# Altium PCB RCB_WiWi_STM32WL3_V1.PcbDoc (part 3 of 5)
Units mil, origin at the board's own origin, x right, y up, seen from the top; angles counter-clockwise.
Board outline 1250.1 x 2647.64 mil, 10 copper layers (L01-TOP, L02-GND, L03-SIG, L04-GND, L05-PWR, L06-PWR, L07-GND, L08-SIG, L09-GND, L10-BOT), stack 62.1 mil thick; 342 components, 203 nets, 969 pads, 708 vias.
Unrouted connection lines stored in the file: 108.
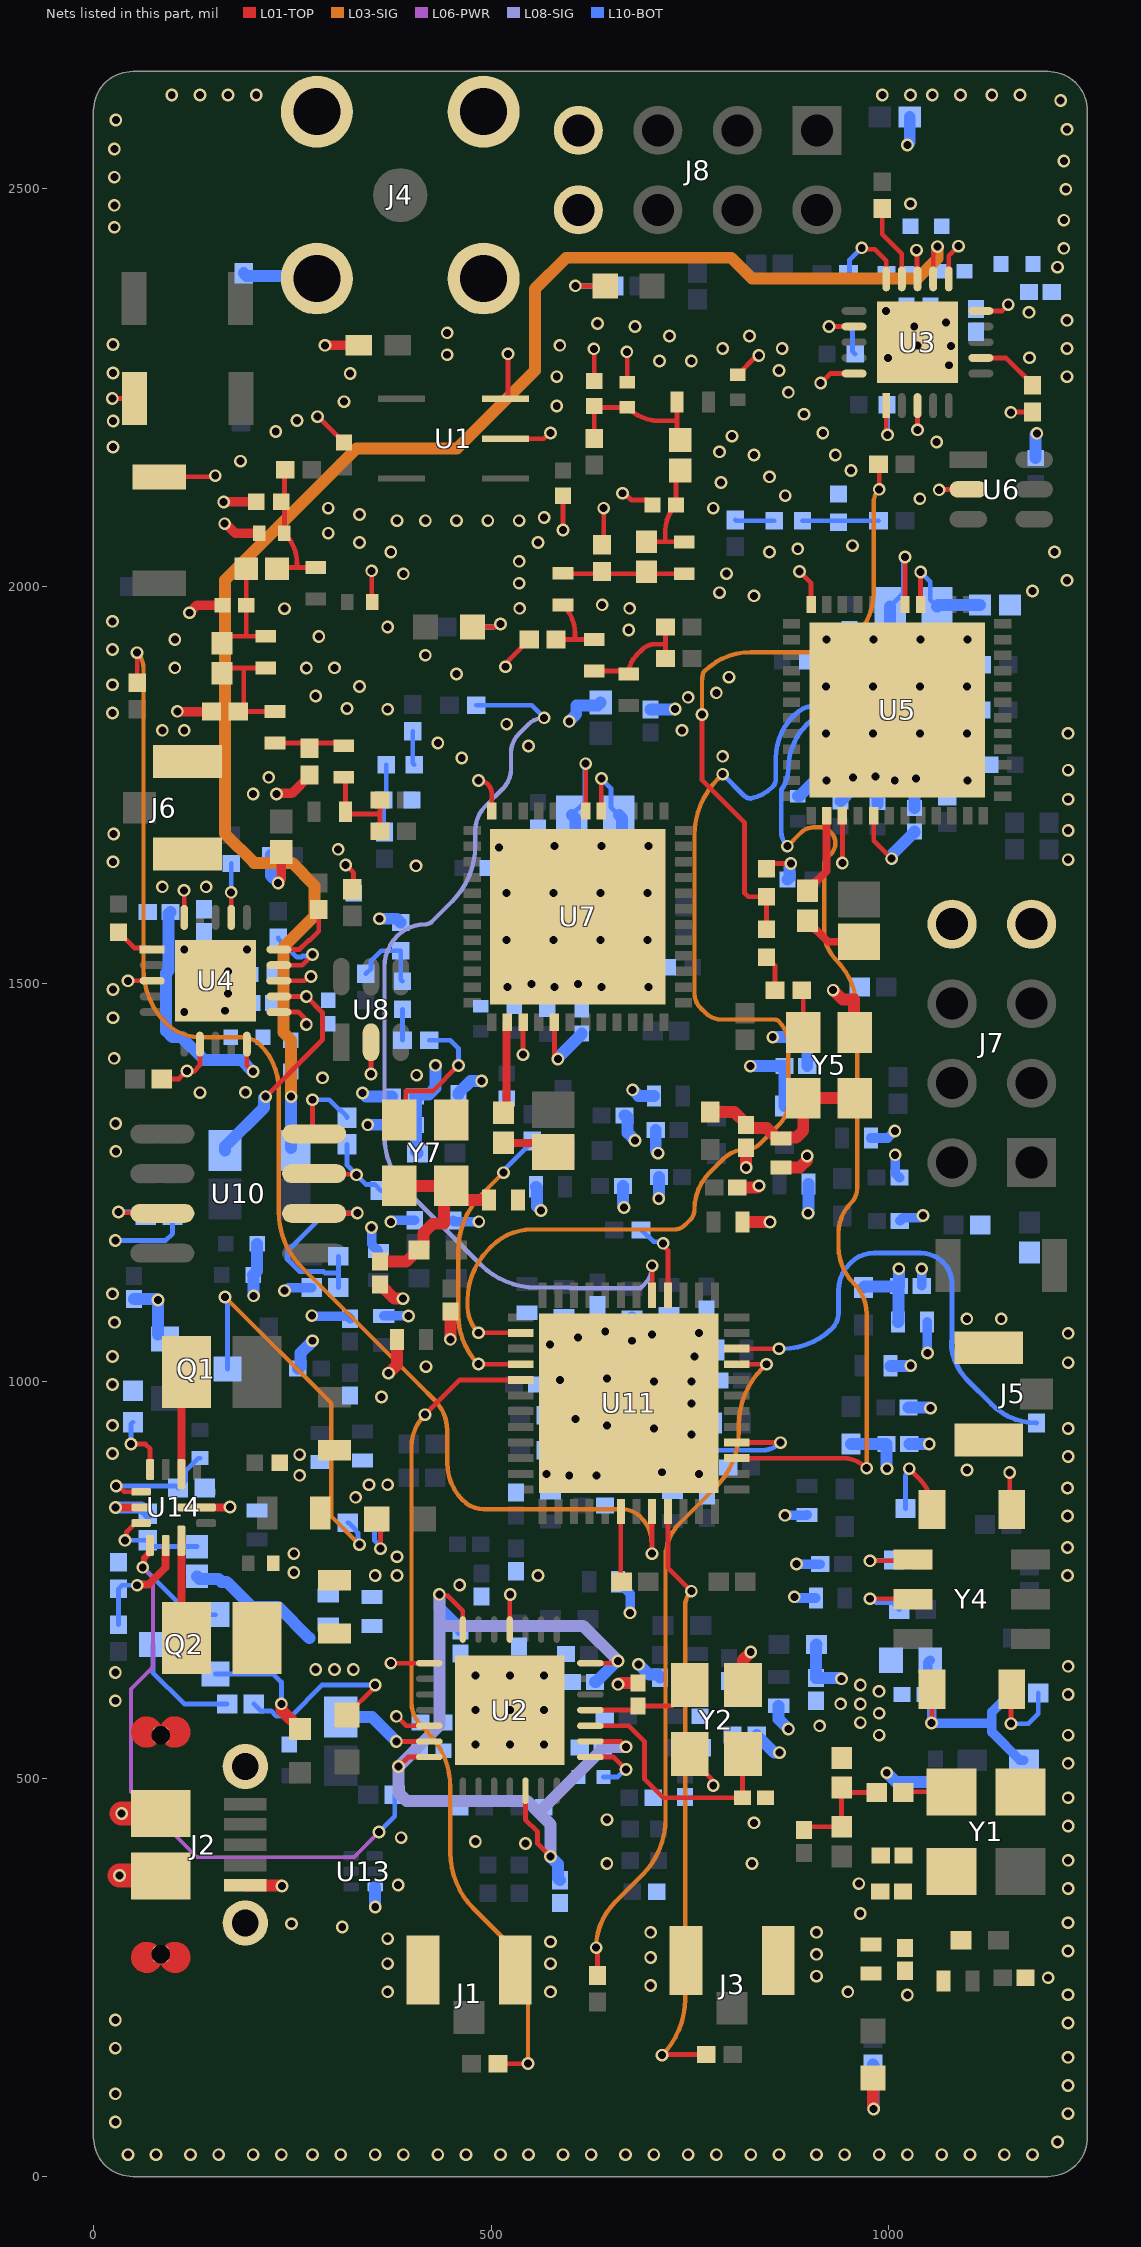
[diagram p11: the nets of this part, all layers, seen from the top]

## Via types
v1: diameter 16, hole 10, L01-TOP to L10-BOT, tented both sides, 699 vias
v2: diameter 16, hole 10, L01-TOP to L10-BOT, 9 vias

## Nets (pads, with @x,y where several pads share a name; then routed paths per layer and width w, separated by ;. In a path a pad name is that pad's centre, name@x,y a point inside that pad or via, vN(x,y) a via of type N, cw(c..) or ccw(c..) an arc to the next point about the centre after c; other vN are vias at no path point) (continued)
GND: C1.2 C2.2 C3.1 C5.2 C6.2 C7.2 C9.2 C10.2 C11.2 C12.2 C13.2 C14.1 C16.2 C17.2 C18.2 C20.2 C22.2 C23.2 C24.2 C25.2 C26.2 C27.2 C28.2 C29.2 C30.2 C31.2 C32.2 C33.2 C34.2 C35.2 C36.2 C37.2 C38.1 C39.2 C40.2 C41.2 C42.2 C43.2 C44.2 C45.1 C46.2 C47.2 C48.1 C49.2 C50.2 C51.2 C52.2 C53.1 C54.1 C55.2 C56.2 C57.1 C58.2 C59.2 C60.2 C61.1 C62.2 C63.2 C64.2 C65.2 C66.2 C67.2 C68.2 C69.2 C70.2 C71.2 C72.2 C73.2 C74.2 C75.2 C76.2 C77.2 C78.2 C79.2 C80.2 C81.2 C82.2 C83.2 C84.2 C85.2 C86.2 C87.2 C88.2 C89.2 C90.2 C91.2 C92.2 C93.2 C94.2 C95.2 C96.2 C97.2 C98.2 C99.2 C100.2 C101.2 C102.2 C103.2 C104.2 C105.2 C106.2 C107.2 C108.2 C109.2 C110.2 C111.2 C112.2 C113.2 C114.2 C115.2 C116.1 C117.2 C118.2 C119.2 C120.2 C121.2 C122.2 C123.1 C124.1 C125.2 C126.2 C127.2 C128.2 C129.2 C130.2 C131.2 C132.2 C133.2 C134.2 C135.2 C136.2 C137.2 C138.2 C139.2 C140.2 C141.1 C142.2 C143.2 C144.2 C145.2 C146.2 C147.2 C148.2 C149.2 C150.2 C151.2 C152.2 C153.2 C154.2 C155.2 C156.2 C157.1 C158.2 C159.2 D5.1 J1.2 J1.3 J2.5 J2.6 J2.7 J2.8 J2.9 J2.10 J2.11 J3.2 J3.3 J4.2 J4.3 J4.4 J4.5 J5.2 J5.3 J6.2 J6.3 J7.7 J7.8 J8.7 J8.8 Q1.2 Q2.2 R8.1 R10.1 R24.1 R25.1 R30.2 R45.2 R46.2 R56.1 R60.1 R61.1 R70.1 R73.2 R75.2 R77.1 R84.1 R88.1 R92.2 R97.1 R98.1 R100.2 R105.1 R109.1 R113.2 SW2.2 SW4.2 U1.1 U1.2 U2.18 U2.22 U2.26 U2.29 U3.3 U3.13 U3.21 U4.3 U4.13 U4.21 U5.24 U5.39 U5.49 U6.2 U7.24 U7.39 U7.49 U8.2 U10.4 U11.49 U13.3 U14.2 U14.9 Y1.2 Y2.2 Y2.4 Y4.5 Y5.2 Y7.2 | length 4514
  L01-TOP w6: v1(23.75,2236.22) SW4.2@51.71,2236.22 ; v1(43.31,1503.94) U4.3@73.82,1503.94 ; SW2.2@82.68,2137.8 151.66,2137.8 v1(153.13,2139.27) ; U4.13@233.27,1503.94 265.65,1503.94 270.97,1509.25 v1(273.68,1509.25) ; v1(275.59,1354.33) 275.59,1313.39 U10.4@277.56,1311.42 ; v1(281.63,2213.4) 282.66,2213.4 C12.2@314.96,2181.1 ; v1(317.22,1649.61) 327.17,1639.65 327.17,1620.82 R113.2@325.45,1619.09 ; U8.2@349.07,1426.54 349.07,1386.89 v1(349.19,1386.77) ; v1(349.85,2019.64) 350.12,2019.37 350.12,1980.58 C9.2@350.39,1980.32 ; v1(374.02,645.67) U2.22@422.24,645.67 ; v1(380.93,578.74) 381.35,578.74 393.16,566.93 U2.26@422.24,566.93 ; v1(484.25,1755.91) cw(c484.25,1739.17) 500.98,1739.17 U7.24@500.98,1717.51 ; U1.2@518.26,2185.79 566.29,2185.79 573.41,2192.91 v1(574.8,2192.91) ; U1.1@518.26,2235.79 ccw(c510.65,2243.39) 521.41,2243.39 v1(521.41,2292.53) ; v1(518.36,1898.94) 518.36,1903.34 C16.2@548.09,1933.07 ; U2.18@523.62,687.99 523.62,731.46 v1(524.2,732.03) ; v1(540.26,1411) 540.35,1411.1 U7.39@540.35,1451.76 ; v1(590.55,2070.87) C30.2@590.55,2114.17 ; v1(629.28,2298.83) 629.94,2298.16 C29.2@629.94,2258.26 ; C17.2@639.74,2052.49 641.73,2054.48 v1(641.73,2098.43) ; v1(665.35,2117.13) 668.06,2117.13 676.52,2108.66 696.61,2108.66 C18.2@702.91,2102.36 ; v1(670.82,2295.08) 671.32,2294.59 C28.2@671.32,2256.53 ; Y2.2@750,531.5 750,527.56 777.61,499.94 777.61,493.59 v1(779.53,491.68) ; C20.2@810.41,2266.49 834.31,2290.39 v1(836.91,2290.39) ; R84.1@846.64,1644.99 853.06,1651.41 v1(877.05,1651.41) ; v1(888.05,2018.66) 902.56,2004.16 U5.24@902.56,1977.35 ; v1@941.93,1652.09 U5.39@941.93,1711.61 ; v1(1035.22,2422.85) 1035.82,2422.26 1035.82,2387.41 U3.13@1036.42,2386.81 ; v1(1036.42,2196.85) U3.3@1036.42,2227.36 ; v1(1063.69,2121.47) 1063.98,2121.76 1100.08,2121.76 U6.2@1100.37,2122.05 ; v1(1152.35,885.45) 1152.35,841.55 Y4.5@1154.72,839.17 ; v1(1153.76,2218.98) 1154.28,2219.49 R61.1@1181.1,2219.49
  L01-TOP w10: v1(27.78,841.6) 59.8,841.6 U14.2@59.86,841.54 ; U14.9@129.74,841.54 129.82,841.61 171.38,841.61 v1(171.81,842.04)
  L01-TOP w12: v1(105.42,1842.82) 105.72,1842.52 C6.2@148.48,1842.52 ; v1(120.69,1966.85) 130.22,1976.38 C7.2@162.41,1976.38 ; v1(163.8,2106.16) 163.95,2106.3 C11.2@204.72,2106.3 ; v1(165.01,2078.93) 166.1,2078.93 178.1,2066.93 C10.2@208.66,2066.93 ; v1(230.2,1738.91) 230.97,1739.67 249.51,1739.67 271.65,1761.81 C5.2@271.65,1762.65 ; v1(232.28,1626.97) 232.28,1628.05 236.22,1631.99 C3.1@236.22,1665.75 ; v1(291.34,2303.15) D5.1@333.66,2303.15
  L01-TOP w15: J2.5@190.94,366.14 236.46,366.14 v1(237.21,365.39) ; v1(236.34,594.49) 236.53,594.3 236.53,586.3 C105.2@259.84,562.99 ; C150.2@360.66,1121.93 378.4,1104.19 v1(389.43,1104.19) ; v1(371.21,1010.36) 381.91,1021.06 C147.2@381.91,1052.98 ; v1(448.82,1052.98) C148.2@448.82,1087.97 ; v1(659.8,619.07) 661.46,620.73 C39.2@685.04,620.73 ; C132.2@809.67,1244.09 834.92,1244.09 v1(836.98,1246.15) ; C131.2@816.44,1200.79 816.78,1200.44 v1(850.88,1200.44) ; Y2.4@816.93,618.11 816.93,649.89 v1(826.71,659.67) ; v1(820.9,1268.97) C134.2@820.9,1293.95 ; C133.2@864.73,1268.97 865.08,1269.32 888.35,1269.32 897.45,1278.41 897.45,1283.27 v1(897.64,1283.46) ; v1(930.35,1492.13) 930.62,1492.13 942.43,1480.32 956.69,1480.32 956.69,1439.96 Y5.2@957.68,1438.98
  L01-TOP w30: v1(32.87,378.6) 84,378.6 J2.10@84.65,377.95 ; v1(35.43,456.69) J2.9@84.65,456.69
  L10-BOT w6: v1(27.56,1177.17) 90.55,1177.17 99.41,1186.02 R25.1@99.41,1208.66 ; Q2.2@153.54,631.89 226.38,631.89 236.34,621.93 v1(236.34,594.49) ; v1(275.59,1354.33) 296.26,1354.33 309.1,1341.49 310.09,1341.49 318.9,1332.68 R30.2@318.9,1331.69
  L10-BOT w12: v1(240.16,1114.17) 241.24,1114.17 245.18,1118.11 R24.1@274.61,1118.11 ; v1(274.61,1082.68) 275.37,1081.91 319.93,1081.91 C66.2@322.92,1078.92 ; v1(349.74,1193.61) 349.74,1172.4 C71.2@358.27,1163.88 ; C64.2@365.1,1082.44 v1(396.16,1082.44) ; v1(374.02,1200.79) 375.1,1200.79 377.12,1202.81 C96.2@404.08,1202.81 ; C95.2@452.61,1202.45 454.09,1200.97 v1(484.64,1200.97) ; C68.2@659.94,748.03 674.89,733.09 v1(674.89,708.92) ; v1(869.63,831.58) 869.93,831.88 897.34,831.88 C114.2@897.64,832.18 ; v1(881.46,729.09) 882.88,727.66 C112.2@908.51,727.66 ; v1(884.18,770.47) 884.52,770.13 C113.2@914.13,770.13 ; C90.2@977.72,1306.2 999,1306.2 1007.76,1314.96 v1(1007.87,1314.96) ; v1(1008.34,1285.07) 1008.34,1261.84 C91.2@1013.76,1256.41 ; C93.2@1014.19,1202.03 1018.27,1206.11 1039.68,1206.11 1042.22,1208.66 v1(1043.31,1208.66) ; C79.2@1041.78,1120.31 v1(1041.78,1141.73) ; C73.2@1048.55,1074.8 1048.55,1036.39 v1(1049.06,1035.87)
  L10-BOT w15: v1(27.78,841.6) 60.3,841.6 62.94,838.96 63.93,838.96 68.24,834.65 R56.1@68.24,833.66 ; C55.2@51.18,1103.72 79.73,1103.72 v1(81.09,1102.36) 80.89,1102.17 Q1.2@80.89,1059.24 ; R100.2@188.98,2394.03 192.39,2390.62 277.49,2390.62 J4.4@280.91,2387.2 ; v1(201.51,1107.67) 201.51,1133.14 C50.2@200.79,1133.86 205.87,1138.94 C120.2@205.87,1173.23 ; C2.2@223.24,1662.33 223.24,1636.22 232.28,1627.18 v1(232.28,1626.97) ; v1(338.5,1362.73) 342.97,1358.27 C74.2@375.37,1358.27 ; v1(344.94,1322.84) C111.2@375.37,1322.83 ; U13.3@354.33,364.17 354.33,339.09 v1(354.4,339.03) ; v1(359.84,1581.97) 381.63,1581.97 R105.1@386.47,1577.12 ; C110.2@458.98,1361.15 458.98,1362.51 474.23,1377.76 488,1377.76 v1(488.19,1377.95) ; C84.2@556.66,1244.94 558.02,1243.58 558.02,1220.3 562.99,1215.33 v1(562.99,1215.06) ; v1(598.43,1830.32) 598.43,1830.59 607.21,1839.37 607.21,1850.39 634.25,1850.39 C14.1@637.8,1853.94 ; C86.2@665.94,1246 665.94,1220.46 667.29,1219.11 v1(667.29,1218.84) ; C72.2@667.93,1334.65 669.29,1334.65 671.87,1332.06 671.87,1312.65 681.1,1303.42 v1(681.1,1303.15) ; v1(677.17,1051.18) C58.2@677.17,1080.22 ; v1(678.13,1366.82) 685.76,1359.19 C100.2@704.75,1359.19 ; v1(685.58,644.14) 685.85,644.14 698.72,631.28 710.02,631.28 712.6,628.7 C108.2@712.6,627.34 ; C13.2@700.79,1845.1 730.91,1845.1 v1(731.7,1845.89) ; C101.2@707.23,1316.46 707.23,1289.89 v1(710.06,1287.06) ; v1(710.96,1230.1) 711.41,1230.54 C103.2@711.41,1257.03 ; C61.1@834.25,555.12 856.26,533.11 v1(862.76,533.11) ; v1(854.33,1433.07) 889.01,1433.07 897.8,1424.28 C75.2@897.8,1396.72 ; C97.2@861.84,592.12 861.84,575.17 v1(874.02,562.99) ; C141.1@872.83,1631.21 875.57,1633.95 875.57,1649.66 877.05,1651.14 v1(877.05,1651.41) ; C140.2@885.83,1736.22 887.8,1736.22 907.26,1755.68 922.05,1755.68 v1(922.24,1755.88) ; v1(898.8,1211.66) 899.28,1212.14 C62.2@899.28,1248.42 ; C143.2@939.61,1729.79 955.17,1745.35 955.17,1759.65 v1(955.36,1759.84) ; v1(983.86,1760.63) 983.86,1760.36 986.02,1758.2 C142.2@986.02,1726.32 ; v1(997.76,507.87) 1009.57,496.06 C54.1@1059.06,496.06 ; C77.2@1002.46,1019.68 1027.79,1019.68 v1(1027.91,1019.81) ; v1(1023.62,2555.12) 1026.72,2558.21 C146.2@1026.72,2590.55 ; C88.2@1025.18,967.29 1051.98,967.29 v1(1052.85,966.42) ; C89.2@1026.05,921.35 v1(1051.18,921.35) ; C136.2@1032.54,1721.29 1032.54,1756.01 1034.45,1757.92 v1(1034.45,1758.19) ; C135.2@1185.04,2161.42 1185.04,2190.98 v1(1186.54,2192.48)
  other v1: 43.31,27.56 78.74,27.56 122.05,27.56 157.48,27.56 200.79,27.56 236.22,27.56 275.59,27.56 311.02,27.56 354.33,27.56 389.76,27.56 433.07,27.56 468.5,27.56 511.81,27.56 547.24,27.56 590.55,27.56 625.98,27.56 669.29,27.56 704.72,27.56 748.03,27.56 783.46,27.56 826.77,27.56 862.2,27.56 909.45,27.56 944.88,27.56 988.19,27.56 1023.62,27.56 1066.93,27.56 1102.36,27.56 1145.67,27.56 1181.1,27.56 1212.6,43.31 27.56,68.5 1225.85,79.03 27.56,103.94 1225.85,114.47 1225.85,149.9 27.56,161.42 1225.85,193.21 27.56,196.85 1023.62,228.35 1225.85,228.64 370.08,232.28 574.8,232.28 948.82,232.28 700.79,240.16 1200.79,250 909.45,251.97 370.08,267.72 574.8,267.72 700.79,275.59 909.45,279.53 1225.85,283.76 574.8,295.28 370.08,299.21 700.79,307.09 909.45,307.09 312.91,313.74 249.04,317.94 1225.85,319.19 964.43,330.71 1225.9,362.2 383.18,366.63 962.6,368.35 645.67,393.7 828.26,393.7 1225.9,397.64 543.31,418.75 480.31,421.26 387.01,426.24 1225.9,440.94 830.71,444.88 645.96,448.82 1225.9,476.38 1225.9,519.68 988.19,555.12 1225.9,555.12 913.39,566.93 988.19,582.68 939.81,594.49 27.56,598.43 1225.9,606.3 988.07,610.24 27.56,633.86 1225.9,641.73 460.63,744.09 354.33,755.91 381.89,755.91 559.06,755.91 1225.07,755.84 251.97,759.84 381.89,779.53 251.97,783.46 1225.07,791.27 1225.07,830.64 329.8,854.26 1225.07,866.08 346.46,870.08 370.08,870.08 259.35,881.89 598.43,881.89 632.9,881.89 569.96,883.86 761.81,883.86 715.06,885.83 1098.8,888.77 1225.9,905.51 259.35,907.87 23.99,909.45 751.97,933.07 704.72,940.94 1225.9,940.94 23.99,944.88 645.67,944.88 606.3,952.76 751.97,972.44 362.2,980.32 23.99,996.04 704.72,1000 751.97,1000 586.61,1001.97 645.67,1003.94 418.33,1018.56 1225.9,1023.62 23.99,1031.48 755.91,1031.5 574.14,1046.34 609.57,1055.12 702.76,1059.06 1225.9,1060.5 761.81,1061.02 643.7,1062.99 26.48,1074.38 1098.43,1078.74 1141.73,1078.74 23.8,1110.27 28.16,1289.41 27.93,1324.4 134.03,1363.19 191.16,1363.68 288.05,1381.89 406.5,1385.21 25.96,1406.38 24.45,1457.48 114.17,1464.57 165.68,1466.27 169.29,1488.19 24.45,1492.91 520.67,1496.03 579.72,1496.03 638.78,1496.03 697.83,1496.03 551.18,1500 609.25,1500 169.29,1515.75 114.17,1543.31 192.91,1543.31 519.68,1555.1 578.74,1555.1 637.8,1555.1 696.85,1555.1 519.68,1614.17 578.74,1614.17 637.8,1614.17 696.85,1614.17 86.61,1622.05 141.73,1622.05 405.71,1648.48 941.93,1652.09 24.6,1653.55 1225.9,1656.25 307.73,1669.29 509.95,1671.66 579.72,1673.24 638.78,1673.24 697.83,1673.24 25.43,1688.58 1225.9,1692.91 1225.9,1732.28 200.79,1738.91 1007.8,1756.01 1099.4,1755.88 220.47,1759.84 1225.9,1768.84 463.17,1784.29 791.34,1786.2 547.24,1799.21 433.07,1803.15 921.26,1814.95 980.31,1814.95 1039.37,1814.95 1098.42,1814.95 1225.77,1815.21 86.61,1818.9 114.17,1818.9 740.16,1818.9 519.68,1826.77 24.04,1840.86 370.08,1845.47 318.9,1846.46 748.03,1860.48 279.53,1862.2 783.46,1866.14 334.65,1874.02 921.26,1874.02 980.31,1874.02 1039.37,1874.02 1098.42,1874.02 24.04,1876.3 799.21,1885.83 456.69,1889.76 267.72,1897.44 102.36,1897.64 303.15,1897.64 417.44,1913.39 24.04,1920.59 102.36,1933.07 922.24,1933.09 981.3,1933.09 1040.35,1933.09 1099.4,1933.09 283.46,1937.01 673.23,1945.28 370.08,1949.06 24.04,1956.02 240.16,1972.05 535.97,1972.44 674.43,1972.44 639.74,1976.77 830.71,1988.19 787.4,1992.13 1181.1,1994.24 535.43,2003.94 1224.41,2007.62 389.76,2015.75 796.26,2015.96 535.43,2031.5 374.02,2043.31 850.39,2043.31 1208.66,2043.31 885.83,2047.24 954.72,2051.18 334.65,2055.12 559.06,2055.12 295.28,2066.93 381.89,2082.68 417.32,2082.68 456.69,2082.68 496.06,2082.68 535.43,2082.68 566.93,2086.61 334.65,2090.55 295.28,2098.43 779.53,2098.43 1039.37,2110.24 870.08,2114.17 789.37,2130.71 850.39,2137.8 952.76,2145.67 185.04,2157.48 830.71,2165.35 933.07,2165.35 787.4,2169.29 24.5,2175.22 1060.47,2181.56 803.15,2188.98 917.32,2192.91 229.27,2194.88 24.83,2208.07 255.91,2208.66 893.7,2216.54 582.68,2226.76 314.96,2232.28 874.02,2244.09 582.68,2263.78 1224.41,2263.78 24.61,2268.36 322.83,2267.72 862.2,2271.65 1075.79,2278.14 711.8,2283.46 751.97,2283.46 999.49,2287.4 1177.17,2287.58 444.88,2291.34 791.34,2299.21 866.14,2299.21 1224.41,2299.21 1078.74,2302.17 586.61,2303.15 1036.42,2303.15 24.5,2304.25 724.41,2314.96 825.17,2314.96 444.88,2318.9 681.1,2326.77 1032.34,2326.77 633.86,2330.71 1072.29,2331.69 1224.41,2334.65 1176.67,2344.7 997.05,2346.46 1212.6,2401.57 1220.47,2425.2 26.3,2451.73 1220.47,2460.63 26.3,2479.29 1027.56,2481.3 1222.92,2499.49 26.3,2514.72 1220.47,2534.92 26.3,2550.15 1224.41,2574.8 28.11,2586.61 1216.44,2611.14 98.43,2618.11 133.86,2618.11 169.29,2618.11 204.72,2618.11 992.13,2618.11 1027.56,2618.11 1055.12,2618.11 1090.55,2618.11 1129.92,2618.11 1165.35,2618.11
  other v2: 480.31,543.31 523.62,543.31 566.93,543.31 480.31,586.61 523.62,586.61 566.93,586.61 480.31,629.92 523.62,629.92 566.93,629.92
NetC4_1: C4.1 C6.1 L18.2 L19.1 | length 163.2
  L01-TOP w6: C4.1@161.42,1890.61 161.42,1897.44 188.98,1897.44 ; C6.1@182.23,1842.52 C6.1@188.98,1842.52 ; L19.1@216.54,1897.44 188.98,1897.44 ; L18.2@228.35,1842.72 228.35,1842.52 C6.1@188.98,1842.52 ; C6.1@188.98,1842.52 188.98,1897.44
NetC4_2: C4.2 C7.1 C8.2 L19.2 | length 141.1
  L01-TOP w6: C4.2@161.42,1928.29 161.42,1937.2 192.22,1937.2 ; C8.2@192.28,2022.09 192.28,1976.43 C7.1@192.22,1976.38 192.22,1937.2 ; L19.2@208.66,1937.2 192.22,1937.2
NetC5_1: C5.1 L17.2 L18.1 | length 90
  L01-TOP w6: L18.1@228.35,1802.95 314.96,1802.95 L17.2@314.96,1799.61
NetC8_1: C8.1 C10.1 C11.1 L20.2 R4.1 | length 176.8
  L01-TOP w6: C8.1@230.86,2022.09 232.59,2023.82 256.06,2023.82 ; R4.1@241.08,2146.62 240.16,2145.69 C10.1@240.16,2066.93 cw(c201.76,2028.53) 256.06,2028.53 256.06,2023.82 ; L20.2@279.53,2023.82 256.06,2023.82
NetC15_1: C15.1 C17.1 L23.2 L24.1 | length 153
  L01-TOP w6: L23.2@590.53,2016.54 590.53,2015.96 L24.1@742.93,2015.96
NetC15_2: C15.2 C18.1 C19.2 L24.2 | length 143.1
  L01-TOP w6: C15.2@695.54,2056.23 719.23,2056.23 ; C19.2@738.03,2145.67 732.72,2140.36 C18.1@732.72,2102.36 ccw(c765.26,2069.81) 719.23,2069.81 719.23,2056.23 ; L24.2@742.93,2055.72 742.93,2056.23 719.23,2056.23
NetC16_1: C16.1 L22.2 L23.1 | length 95.9
  L01-TOP w6: C16.1@581.83,1933.07 605.78,1933.07 ; L23.1@590.53,1976.77 cw(c553.72,1939.96) 605.78,1939.96 605.78,1933.07 ; L22.2@629.92,1933.27 629.72,1933.07 605.78,1933.07
NetC19_1: C19.1 C28.1 C29.1 L25.2 R9.1 | length 201.4
  L01-TOP w6: R9.1@629.92,2186.02 C29.1@629.94,2226.76 ccw(c634.1,2230.92) 634.1,2225.04 C28.1@671.32,2225.04 ccw(c711.8,2265.52) 711.8,2208.27 733.89,2208.27 ; L25.2@733.89,2231.89 733.89,2208.27 ; C19.1@738.03,2184.25 733.89,2184.25 733.89,2208.27
NetC21_1: C21.1 R3.1 R7.2 R8.2 | length 144.9
  L01-TOP w6: C21.1@893.7,435.65 898.01,439.96 R3.1@940.94,439.96 R8.2@940.94,489.17 947.21,482.91 R7.2@984.97,482.91
NetC24_1: C24.1 C25.1 C26.1 C27.1 L2.2 Y1.4
NetC31_1: C31.1 C32.1 C33.1 C34.1 U2.5 U2.9 U2.14 U2.21 U2.28 | length 1351.5
  L01-TOP w6: v1(383.71,515.75) 384.13,515.75 395.94,527.56 U2.28@422.24,527.56 ; v1(435.04,732.28) 436.95,730.37 445.74,730.37 464.57,711.54 U2.21@464.57,687.99 ; U2.5@543.31,485.24 543.31,459.12 543.31,456.63 543.31,448.76 558.61,433.46 558.61,418.75 v1(574.8,402.56) ; U2.9@625,547.24 663.06,547.24 v1(669.83,540.47) ; U2.14@625,645.67 654.31,645.67 657.1,648.45 v1(659.8,648.45)
  L08-SIG w15: v1(435.04,732.28) 435.04,692.42 ; v1(574.8,402.56) 574.8,443.01 560.09,457.73 ; v1(659.8,648.45) 615.83,692.42 435.04,692.42 ; v1(669.83,540.47) 642.83,540.47 560.09,457.73 ; 435.04,692.42 435.04,567.07 v1(383.71,515.75) 383.71,482.43 393.7,472.44 545.37,472.44 560.09,457.73
  L10-BOT w15: v1(435.04,732.28) 435.23,732.09 435.23,714.71 461.78,688.16 C31.1@461.78,686.8 ; v1(574.8,402.56) 574.8,402.29 584.03,393.06 584.03,375.24 C32.1@586.61,372.66 ; C34.1@630.84,622.05 632.2,622.05 658.41,648.26 659.61,648.26 v1(659.8,648.45) ; C33.1@640.46,539.33 641.41,540.28 669.64,540.28 v1(669.83,540.47)
NetC39_1: C39.1 U2.11 Y2.1 | length 140.4
  L01-TOP w6: U2.11@625,586.61 679.79,586.61 C39.1@685.04,591.87 727.69,591.87 750,614.17 Y2.1@750,618.11
NetC43_1: C43.1 U2.10 Y2.3 | length 311.8
  L01-TOP w6: U2.10@625,566.93 673.23,566.93 692.91,547.24 692.91,500 716.54,476.38 C43.1@816.28,476.38 816.28,530.84 Y2.3@816.93,531.5
NetC47_1: C47.1 C49.1 FB1.2 U2.27 | length 123.9
  L01-TOP w6: v1(380.93,547.24) U2.27@422.24,547.24
  L10-BOT w15: FB1.2@311.02,577.8 350.38,577.8 v1(380.93,547.24)
NetC51_1: C51.1 C52.1 FB3.2 R55.2 U3.12 | length 2016.9
  L01-TOP w6: U3.12@1056.1,2386.81 1056.1,2419.16 1061.55,2424.61 v1(1061.55,2427.31)
  L03-SIG w15: v1(248.64,1358.27) 248.64,1429.24 238.9,1438.98 238.9,1545.99 277.88,1584.97 277.88,1624.14 249.78,1652.25 202.08,1652.25 165.35,1688.98 165.35,2007.87 330.71,2173.23 457.15,2173.23 555.12,2271.2 555.12,2374.02 594.49,2413.39 802.17,2413.39 828.44,2387.11 1036.12,2387.11 1061.36,2412.35 1061.36,2427.12 v1(1061.55,2427.31)
  L10-BOT w6: FB3.2@248.64,1293.73 FB3.2@251.97,1290.4
  L10-BOT w15: FB3.2@248.64,1293.73 v1(248.64,1358.27)
NetC56_1: C56.1 C57.2 FB2.1 R27.1 Y4.10 | length 319.9
  L01-TOP w6: v1(1054.1,570.39) 1054.72,571.02 Y4.10@1054.72,612.8
  L10-BOT w12: C56.1@1052.36,649.61 1049.15,646.39 1049.15,609.52 C57.2@1045.93,606.3 1047.24,606.3 1050.54,603 1050.54,601.68 1054.1,598.13 v1(1054.1,570.39) 1128.66,570.39 1129.92,571.66 ; R27.1@1154.72,608.07 1153.74,608.07 1129.92,584.26 1129.92,571.66 ; FB2.1@1170.28,523.62 1165.35,523.62 1129.92,559.06 1129.92,571.66
NetC61_2: C61.2 R47.1 R48.1
NetC117_1: C117.1 R55.1 R60.2 U3.11 | length 46.2
  L01-TOP w6: U3.11@1075.79,2386.81 1075.79,2415.62 v1(1088.07,2427.91)
NetC118_1: C118.1 C119.1 U3.10 U3.20 | length 84.6
  L01-TOP w6: v1(914.7,2255.91) 915.12,2255.91 926.93,2267.72 U3.20@956.69,2267.72 ; U3.10@1116.14,2346.46 1142.72,2346.46 v1(1150.59,2354.33)
NetC121_1: C121.1 C122.1 FB4.2 R66.2 U4.12 | length 287.5
  L01-TOP w6: v1(216.54,1358.27) 288.05,1429.78 288.05,1463.92 v1(267.72,1484.25) U4.12@233.27,1484.25
  L10-BOT w15: FB4.2@165.35,1290.4 165.35,1295.28 214.62,1344.54 214.62,1356.35 v1(216.54,1358.27)
NetC125_1: C125.1 R66.1 R70.2 U4.11 | length 44.3
  L01-TOP w6: U4.11@233.27,1464.57 258.02,1464.57 265.8,1456.78 265.8,1450.99 v1(267.72,1449.08)
NetC126_1: C126.1 C127.1 U4.10 U4.20 | length 354.4
  L01-TOP w6: v1(113.88,1617.65) 114.17,1617.36 U4.20@114.17,1583.66 ; U4.10@192.91,1424.21 192.91,1397.64 v1(200.79,1389.76)
  L10-BOT w15: C126.1@97.07,1590.55 96.95,1590.55 94.37,1587.97 94.37,1516.62 91.38,1513.62 91.38,1441.03 99.34,1433.07 110.59,1433.07 139.14,1404.53 185.75,1404.53 200.52,1389.76 v1(200.79,1389.76)
NetC128_1: C128.1 U5.17 Y3.1 | length 147.2
  L01-TOP w6: U5.17@1040.35,1977.35 1040.35,2018.02 v1(1040.45,2018.11)
  L10-BOT w6: v1(1040.45,2018.11) 1052.47,2006.09 1052.47,1983.4 Y3.1@1061.02,1974.85
  L10-BOT w15: Y3.1@1061.02,1974.85 1062.56,1976.38 C128.1@1115.02,1976.38
NetC129_1: C129.1 U5.18 Y3.2 | length 186.2
  L01-TOP w6: U5.18@1020.67,1977.35 v1(1020.66,2036.87)
  L10-BOT w6: Y3.2@1001.97,1974.85 1018.65,1991.53 1018.65,2032.16 1020.66,2034.17 v1(1020.66,2036.87)
  L10-BOT w15: Y3.2@1001.97,1974.85 1001.97,1927.17 1007.87,1921.26 C129.1@1007.87,1920.42
NetC133_1: C133.1 C134.1 L26.2 Y5.1 Y5.4 | length 242.3
  L01-TOP w15: L26.2@775.84,1338.93 806.06,1338.93 820.9,1324.09 C134.1@820.9,1322.73 820.9,1321.37 823.48,1318.79 846.9,1318.79 860.3,1305.39 C133.1@864.73,1305.39 866.09,1306.74 883.93,1306.74 892.72,1315.53 Y5.4@892.72,1356.3 Y5.1@957.68,1356.3
NetC136_1: C136.1 U5.41 | length 109.4
  L01-TOP w6: U5.41@981.3,1711.61 981.3,1680.12 v1(1003.94,1657.48)
  L10-BOT w15: v1(1003.94,1657.48) 1004.13,1657.67 1004.13,1662.23 1032.54,1690.64 C136.1@1032.54,1691.48
NetC144_1: C144.1 U7.17 Y6.1 | length 155
  L01-TOP w6: U7.17@638.78,1717.51 638.78,1758.17 v1(638.88,1758.26)
  L10-BOT w6: v1(638.88,1758.26) 650.9,1746.24 650.9,1722.42 Y6.1@660.72,1712.6
  L10-BOT w15: Y6.1@660.72,1712.6 665.01,1708.31 665.01,1660.92 C144.1@669.29,1656.64
NetC145_1: C145.1 U7.18 Y6.2 | length 190.7
  L01-TOP w6: U7.18@619.09,1717.51 v1(619.09,1777.03)
  L10-BOT w6: Y6.2@601.67,1712.6 618.35,1729.28 618.35,1776.29 v1(619.09,1777.03)
  L10-BOT w15: Y6.2@601.67,1712.6 605.95,1708.31 605.95,1660.92 C145.1@610.24,1656.64
NetC149_1: C149.1 C150.1 L29.2 Y7.1 Y7.4 | length 283.7
  L01-TOP w15: C150.1@360.66,1150.71 393.33,1150.71 407.97,1165.35 L29.2@409.45,1165.35 410.93,1165.35 415.24,1169.67 415.24,1186.89 426.67,1198.32 441.02,1198.32 441.02,1237.28 Y7.1@449.8,1246.06 ; Y7.4@384.84,1246.06 Y7.1@449.8,1246.06 ; C149.1@497.54,1228.35 463.96,1228.35 449.8,1242.5 Y7.1@449.8,1246.06
NetC152_1: C152.1 U7.41 | length 92.9
  L01-TOP w6: U7.41@579.72,1451.76 579.71,1412.6 584.1,1408.22 v1(584.1,1405.51)
  L10-BOT w15: v1(584.1,1405.51) 584.29,1405.7 584.29,1407.13 614.17,1437.01 C152.1@614.17,1437.85
NetD1_1: D1.1 R71.2 | length 95.9
  L01-TOP w15: D1.1@980.31,124.02 980.31,85.83 v1(981.31,84.83)
  L10-BOT w15: R71.2@980.31,140.75 981.12,139.94 981.12,85.02 v1(981.31,84.83)
NetD2_1: D2.1 R72.2 | length 85.3
  L01-TOP w6: v1(606,2377.97) D2.1@643.7,2377.95
  L10-BOT w6: v1(606,2377.97) R72.2@653.54,2377.95
NetD3_1: D3.1 R16.2 | length 74.5
  L01-TOP w6: D3.1@356.3,826.77 360.89,822.18 v1(360.89,789.73)
  L10-BOT w6: R16.2@353.35,822.18 353.35,799.98 360.89,792.44 v1(360.89,789.73)
NetD4_1: D4.1 R17.2 | length 227.1
  L01-TOP w5.5: D4.1@318.9,580.71 354.33,616.14 v1(354.33,618.11)
  L10-BOT w6: R17.2@201.77,594.49 210.58,585.68 223.52,585.68 230.01,579.19 248.48,579.19 287.4,618.11 v1(354.33,618.11)
NetD8_1: D8.1 R93.2 | length 72.2
  L01-TOP w6: D8.1@476.5,1949.06 505.41,1949.06 509.1,1952.76 v1(511.81,1952.76)
  L10-BOT w6: R93.2@477.48,1949.06 502.88,1949.06 ccw(c502.88,1961.68) v1(511.81,1952.76)
NetL1_1: L1.1 L17.1 R1.2 R2.2 | length 130.9
  L01-TOP w6: L17.1@314.96,1759.84 317.13,1759.84 L1.1@317.13,1716.54 317.13,1713.58 360.24,1713.58 ; R1.2@360.24,1691.93 360.24,1713.58 ; R2.2@360.24,1731.3 360.24,1713.58
NetL9_1: L9.1 U14.6 | length 125.3
  L01-TOP w10: U14.6@110.55,799.7 110.55,683.71 L9.1@117.1,677.17
NetL10_1: L10.1 U14.12 | length 119.3
  L01-TOP w10: U14.12@110.55,883.37 110.55,993.45 L10.1@117.1,1000
NetL21_1: L21.1 L22.1 R5.2 R6.2 | length 151
  L01-TOP w6: L22.1@629.92,1893.5 664.67,1893.5 cw(c664.67,1881.41) L21.1@673.23,1889.96 cw(c706.02,1889.96) 682.83,1913.15 690.94,1921.26 cw(c705.2,1907) 705.2,1927.17 719.49,1927.17 ; R5.2@719.49,1909.45 719.49,1927.17 ; R6.2@719.49,1948.82 719.49,1927.17
NetL27_2: L27.2 L28.1 | length 76.1
  L01-TOP w10: L28.1@898.16,1579.45 898.16,1578.6 923.71,1553.05 L27.2@962.83,1553.05
NetL28_2: L28.2 U5.38 | length 104.5
  L01-TOP w10: L28.2@898.16,1617.13 898.16,1617.97 922.24,1642.06 U5.38@922.24,1711.61
NetL30_2: L30.2 L31.1 | length 67.6
  L01-TOP w10: L31.1@515.75,1300.17 566.89,1300.17 L30.2@578.55,1288.51
NetL31_2: L31.2 U7.38 | length 115.9
  L01-TOP w10: L31.2@515.75,1337.85 519.76,1341.87 519.76,1450.85 U7.38@520.67,1451.76
NetQ1_3: Q1.3 R16.1 | length 507.7
  L03-SIG w5.5: v1(165.35,1106.3) 299.21,972.44 299.21,830.13 v1(334.63,794.71)
  L10-BOT w6: v1(165.35,1106.3) 165.35,1103.59 168.54,1100.4 Q1.3@168.54,1015.75 ; R16.1@319.88,822.18 320.87,822.18 329.68,813.37 329.68,812.39 332.72,809.34 332.72,796.62 v1(334.63,794.71)
NetQ2_3: Q2.3 R17.1 | length 145.2
  L10-BOT w6: Q2.3@74.8,669.29 74.8,633.86 114.17,594.49 R17.1@168.31,594.49
NetR7_1: R7.1 Y1.3 | length 61.3
  L01-TOP w6: R7.1@1018.43,482.91 1019.38,483.86 Y1.3@1079.29,483.86
NetR10_2: R10.2 U2.8 | length 83.5
  L01-TOP w6: U2.8@625,527.56 654.08,527.56 v1(669.83,511.81)
  L10-BOT w6: R10.2@641.55,502.53 659.41,502.53 668.69,511.81 v1(669.83,511.81)
NetR11_1: R11.1 U3.17 | length 94.3
  L01-TOP w6: v1(925.08,2326.78) U3.17@956.69,2326.77
  L10-BOT w6: v1(925.08,2326.78) 949.66,2326.78 954.6,2321.85 954.6,2295.68 R11.1@958.09,2292.19
NetR12_1: R12.1 U3.1 | length 73.1
  L01-TOP w6: v1@997.05,2192.19 U3.1@997.05,2227.36
  L10-BOT w6: R12.1@998.03,2228.35 998.57,2227.81 v1(998.57,2190.67)
NetR15_2: R15.2 R56.2 U14.3 | length 128.1
  L01-TOP w6: v1(39.71,800.2) 41.62,802.11 41.62,810.99 52.48,821.85 U14.3@59.86,821.85
  L10-BOT w6: v1(39.71,800.2) R56.2@68.24,800.2 76.16,792.28 R15.2@130.24,792.28
NetR20_1: R20.1 R30.1 U10.3 | length 135.7
  L01-TOP w6: U10.3@277.56,1261.42 278.35,1260.63 329.92,1260.63 v1(330.71,1259.84)
  L10-BOT w6: R30.1@318.9,1298.23 318.9,1272.07 330.71,1260.26 v1(330.71,1259.84) 342.73,1247.82 353.56,1247.82 R20.1@361.22,1240.16
NetR21_1: R21.1 R24.2 U10.2 | length 283.3
  L01-TOP w6: U10.2@277.56,1211.42 331.49,1211.42 v1(331.85,1211.78)
  L10-BOT w6: R24.2@308.07,1118.11 308.07,1136.32 ; R21.1@308.07,1157.48 308.07,1136.32 ; v1(331.85,1211.78) 291.7,1211.78 244.09,1164.17 244.09,1153.06 258.79,1138.37 289.28,1138.37 291.33,1136.32 308.07,1136.32
NetR25_2: R25.2 U10.7 | length 92
  L01-TOP w6: v1(31.53,1213.12) 32.39,1212.27 85.76,1212.27 U10.7@86.61,1211.42
  L10-BOT w6: v1(31.53,1213.12) 61.48,1213.12 R25.2@65.94,1208.66
NetR26_2: R26.2 Y4.6 | length 112
  L01-TOP w6: v1(1026.05,890.24) 1038.89,877.4 cw(c1000.66,839.17) Y4.6@1054.72,839.17
  L10-BOT w6: R26.2@1021.26,840.16 1021.26,878.67 cw(c1037.62,878.67) 1021.98,883.46 cw(c1037.62,878.67) v1(1026.05,890.24)
NetR27_2: R27.2 Y4.1 | length 109
  L01-TOP w6: v1(1154,569.6) 1154,612.07 Y4.1@1154.72,612.8
  L10-BOT w6: v1(1154,569.6) 1175.9,569.6 1188.19,581.89 R27.2@1188.19,608.07
NetR28_1: R28.1 Y4.7 | length 85.7
  L01-TOP w6: v1(976.6,774.46) 1029.38,774.46 Y4.7@1030.9,775.99
  L10-BOT w6: v1(976.6,774.46) 1005.76,774.46 R28.1@1006.89,775.59
NetR29_1: R29.1 Y4.8 | length 97.1
  L01-TOP w6: v1(976.6,726.71) 1030.18,726.71 Y4.8@1030.9,725.99
  L10-BOT w6: v1(976.6,726.71) 979.3,726.71 984.01,722 1004.69,722 R29.1@1013.5,713.19
NetR32_1: R32.1 U11.18 | length 88.8
  L01-TOP w6: U11.18@663.28,836.33 663.28,749.12 R32.1@664.37,748.03
NetR33_1: R33.1 U11.41 | length 1194.6
  L01-TOP w6: U11.41@702.76,1108.44 v1(702.76,1145.67)
  L08-SIG w5.5: v1(566.93,1834.65) ccw(c566.93,1806.13) 546.77,1826.29 535.43,1814.96 ccw(c560.36,1790.04) 525.11,1790.04 525.11,1770.42 cw(c489.69,1770.42) 514.73,1745.38 493.07,1723.72 ccw(c523.88,1692.91) 480.31,1692.91 480.31,1674.49 cw(c380.31,1674.49) 451.03,1603.78 425.7,1578.45 cw(c416.86,1587.28) 416.86,1574.79 ccw(c416.86,1525.66) 382.12,1560.4 382.03,1560.31 ccw(c420.79,1521.55) 365.97,1521.55 365.97,1309.31 ccw(c465.97,1309.31) 395.26,1238.6 486.46,1147.4 ccw(c557.17,1218.11) 557.17,1118.11 598.43,1118.11 ccw(c600.39,1120.08) 600.39,1117.29 688.07,1117.29 693.08,1122.3 ccw(c669.71,1145.67) v1(702.76,1145.67)
  L10-BOT w6: R33.1@481.3,1850.39 551.18,1850.39 v1(566.93,1834.65)
NetR34_2: R34.2 U11.2 | length 1600.3
  L01-TOP w6: v1(484.17,1061.24) 484.28,1061.13 U11.2@537.12,1061.13
  L03-SIG w5.5: v1(484.17,1061.24) cw(c517.32,1094.39) 470.44,1094.39 470.44,1101.43 cw(c562.89,1101.43) 497.52,1166.81 500.77,1170.07 ; 500.8,1170.09 cw(c551.49,1119.35) 551.49,1191.07 730.14,1191.07 ccw(c730.14,1210.8) 744.09,1196.84 750.34,1203.09 ccw(c736.9,1216.54) 755.91,1216.54 cw(c821.25,1216.54) 775.04,1262.74 792.2,1279.9 cw(c820.9,1251.2) 820.9,1291.79 ccw(c820.9,1316.55) 838.41,1299.04 862.2,1322.83 ccw(c833.69,1351.35) 874.02,1351.35 874.02,1424.24 ccw(c833.69,1424.24) 862.2,1452.76 ccw(c856.03,1446.58) 856.03,1455.31 789.64,1455.31 cw(c789.64,1483.59) 769.64,1463.6 763.69,1469.54 cw(c782.5,1488.35) 755.91,1488.35 755.91,1686.92 cw(c855.91,1686.92) 785.19,1757.64 v1(791.34,1763.78)
  L10-BOT w6: v1(791.34,1763.78) 818.21,1736.91 ccw(c826.92,1745.62) 826.92,1733.3 ccw(c816.16,1786.2) 854.33,1748.03 ccw(c844.83,1757.54) 858.27,1757.54 858.27,1783.46 cw(c934.31,1783.46) 880.54,1837.23 881.89,1838.58 cw(c910.4,1810.07) 910.4,1850.39 1035.43,1850.39 ccw(c1035.43,1888.41) 1062.32,1861.53 1062.99,1862.2 1062.99,1871.62 cw(c1089.88,1871.62) 1070.87,1890.63 cw(c1097.29,1864.21) 1097.29,1901.57 R34.2@1117.13,1901.57
NetR35_1: R35.1 U11.33 | length 876.4
  L01-TOP w6: v1(632.24,287.83) 633.86,286.21 R35.1@633.86,252.95 ; U11.33@809.23,1021.65 v1(846.46,1021.65)
  L03-SIG w5.5: v1(632.24,287.83) cw(c712.85,287.83) 655.85,344.83 690.2,379.18 ccw(c619.49,449.89) 719.49,449.89 719.49,778.83 cw(c779.71,778.83) 737.13,821.41 782.47,866.75 ccw(c711.75,937.46) 811.75,937.46 811.75,945.53 cw(c911.75,945.53) 841.04,1016.24 v1(846.46,1021.65)
NetR36_2: R36.2 U11.4 | length 374.7
  L01-TOP w6: v1(484.17,1021.87) 484.28,1021.76 U11.4@537.12,1021.76
  L03-SIG w5.5: v1(484.17,1021.87) cw(c545.18,1082.87) 464.04,1053.55 cw(c469.23,1055.36) 463.77,1054.67 ccw(c448.82,1052.98) 462.11,1060.03 cw(c466.99,1062.57) 461.68,1061.14 cw(c545.18,1082.87) 458.9,1082.87 458.9,1164.39 cw(c558.9,1164.39) 488.19,1235.1 v1(515.75,1262.66)
  L10-BOT w6: v1(515.75,1262.66) 517.66,1264.57 517.66,1267.38 551.85,1301.57 R36.2@551.85,1302.55
NetR37_1: R37.1 U11.28 | length 281.8
  L01-TOP w6: U11.28@811.13,923.12 863.97,923.12 v1(864.08,923.01)
  L10-BOT w6: R37.1@674.21,972.44 701.47,972.44 cw(c701.47,945.56) 720.47,964.57 722.78,962.26 cw(c709.34,948.82) 728.35,948.82 728.35,940.27 ccw(c755.23,940.27) 736.22,921.26 ccw(c755.23,940.27) 755.23,913.39 840.84,913.39 ccw(c840.84,946.26) v1(864.08,923.01)
NetR38_1: R38.1 U11.20 | length 1637.4
  L01-TOP w6: v1(54.71,1916.68) 55.12,1916.27 R38.1@55.12,1878.94 ; v1(702.54,783.38) 702.65,783.49 U11.20@702.65,836.33
  L03-SIG w5.5: v1(54.71,1916.68) cw(c34.7,1896.68) 62.99,1896.68 62.99,1519.02 ccw(c159.91,1519.02) 91.38,1450.49 ccw(c133.43,1492.54) 133.43,1433.07 186.14,1433.07 cw(c186.14,1399.47) 209.9,1423.23 cw(c154.3,1367.63) 232.93,1367.63 232.93,1214 ccw(c332.93,1214) 262.22,1143.29 409.45,996.06 429.13,976.38 cw(c391.11,938.36) 444.88,938.36 444.88,897.92 ccw(c512.09,897.92) 464.57,850.39 ccw(c491.25,877.08) 491.25,839.34 664.78,839.34 cw(c664.78,806.41) 688.07,829.69 cw(c653.14,794.76) 702.54,794.76 v1(702.54,783.38)
NetR39_1: R39.1 U11.40 | length 100.8
  L01-TOP w6: v1(716.54,1173.66) 716.54,1170.96 722.55,1164.94 U11.40@722.55,1110.34
  L10-BOT w6: R39.1@688.54,1190.47 689.52,1190.47 704.42,1175.58 714.62,1175.58 v1(716.54,1173.66)
NetR40_1: R40.1 U11.34 | length 603.5
  L01-TOP w6: U11.34@809.34,1041.23 862.18,1041.23 v1(862.29,1041.12)
  L10-BOT w6: v1(862.29,1041.12) 866.84,1041.12 ccw(c866.84,1129.23) 929.13,1066.93 ccw(c910.12,1085.94) 937.01,1085.94 937.01,1114.17 cw(c984.53,1114.17) 950.93,1147.78 952.76,1149.61 cw(c981.27,1121.09) 981.27,1161.42 1040.38,1161.42 cw(c1040.38,1121.09) 1068.9,1149.61 cw(c1042.91,1123.62) 1079.66,1123.62 1079.66,1048.14 ; 1078.74,1051.18 ccw(c1148.96,1051.18) 1099.3,1001.54 1129.65,971.19 ccw(c1186.02,1027.56) R40.1@1186.02,947.84
NetR41_1: R41.1 U11.27 | length 1450.5
  L01-TOP w6: U11.27@811.02,903.54 942.03,903.54 cw(c942.03,860.53) v1(972.44,890.95)
  L03-SIG w5.5: v1(872.77,1673.23) 889.94,1690.4 cw(c905.51,1674.83) 905.51,1696.85 915.69,1696.85 cw(c915.69,1683.41) 925.2,1692.91 927.5,1690.61 cw(c914.06,1677.17) 933.07,1677.17 cw(c912.63,1677.17) 927.08,1662.71 922.24,1657.87 ccw(c929.42,1650.69) 919.27,1650.69 919.27,1564.81 ccw(c966.39,1564.81) 933.07,1531.5 cw(c866.54,1464.96) 960.63,1464.96 960.63,1243.42 cw(c933.75,1243.42) 952.76,1224.41 ccw(c990.77,1186.39) 937.01,1186.39 937.01,1170.29 ccw(c1004.22,1170.29) 956.69,1122.76 cw(c918.67,1084.74) 972.44,1084.74 v1(972.44,890.95)
  L10-BOT w6: v1(872.77,1673.23) cw(c891.48,1691.94) 865.02,1691.94 865.02,1744.09 ccw(c832.42,1769.66) 873.85,1769.66 cw(c954.3,1769.66) 897.41,1826.55 897.64,1826.77 cw(c916.65,1807.76) 916.65,1834.65 1092.9,1834.65 ccw(c1092.9,1868.22) R41.1@1116.65,1844.48
NetR42_1: R42.1 U11.21 | length 762.1
  L01-TOP w6: v1(714.98,152.57) 715.95,153.54 R42.1@770.67,153.54 ; U11.21@722.44,836.44 722.44,765.75 v1(751.97,736.22)
  L03-SIG w5.5: v1(714.98,152.57) ccw(c644.68,222.87) 744.09,222.87 744.09,717.21 cw(c770.98,717.21) v1(751.97,736.22)
NetR44_2: R44.2 U11.5 | length 1043.3
  L01-TOP w6: v1(416.87,958.18) 460.67,1001.97 U11.5@537.23,1001.97 ; R44.2@508.86,141.73 546.21,141.73 v1(546.51,142.04)
  L03-SIG w5.5: 412.32,566.94 cw(c442.28,596.88) 399.92,596.88 399.92,917.25 cw(c457.8,917.25) v1(416.87,958.18) ; 412.33,566.93 419.64,559.62 cw(c348.93,488.91) 448.93,488.91 448.93,407.45 ccw(c548.93,407.45) 478.22,336.74 519.68,295.28 cw(c454.92,230.51) 546.51,230.51 v1(546.51,142.04)
NetR57_1: R57.1 U3.15 | length 99.3
  L01-TOP w6: v1(966.28,2425.88) 968.19,2423.97 982.74,2423.97 997.05,2409.66 U3.15@997.05,2386.81
  L10-BOT w6: R57.1@949.8,2393.7 950.79,2394.68 950.79,2410.39 v1(966.28,2425.88)
NetR58_2: R58.2 R77.2 U14.1 | length 163.6
  L01-TOP w6: v1(28.54,868.44) 31.25,868.44 38.46,861.22 U14.1@59.86,861.22
  L10-BOT w6: v1(28.54,868.44) 104.01,868.44 R77.2@106.3,866.14 107.28,866.14 116.09,874.95 116.09,887.75 131.89,903.54 R58.2@133.86,903.54
NetR59_1: R59.1 U3.14 | length 98.8
  L01-TOP w6: R59.1@992.13,2475.39 992.13,2443.16 1016.73,2418.55 U3.14@1016.73,2386.81
NetR61_2: R61.2 U3.7 | length 79.8
  L01-TOP w6: U3.7@1116.14,2287.4 1147.64,2287.4 1181.1,2253.94 R61.2@1181.1,2252.95
NetR62_1: R62.1 U4.17 | length 67.9
  L01-TOP w6: U4.17@173.23,1583.66 v1(173.24,1615.27)
  L10-BOT w6: v1(173.24,1615.27) R62.1@173.23,1651.57
NetR63_1: R63.1 U4.1 | length 51.3
  L01-TOP w6: R63.1@31.5,1564.96 51.23,1545.23 71.9,1545.23 U4.1@73.82,1543.31
NetR67_1: R67.1 U4.15 | length 87
  L01-TOP w6: U4.15@233.27,1543.31 259.08,1543.31 270.51,1554.74 272.02,1554.74 283.46,1566.18 R67.1@283.46,1593.5
NetR68_1: R68.1 U4.14 | length 103.1
  L01-TOP w6: U4.14@233.27,1523.62 262.3,1523.62 v1(275.59,1536.92)
  L10-BOT w6: R68.1@232.28,1558.07 232.28,1557.09 255.59,1533.78 261.59,1533.78 262.81,1535 273.68,1535 v1(275.59,1536.92)
NetR69_2: R69.2 U4.7 | length 82.4
  L01-TOP w6: R69.2@85.73,1380.51 107.52,1380.51 117.45,1390.44 v1(117.54,1390.44) 118.21,1389.76 125.98,1389.76 133.86,1397.64 U4.7@133.86,1424.21
NetR79_1: R79.1 R97.2 U14.5 | length 143.4
  L01-TOP w10: v1(55.01,743.71) 56.16,744.86 69.45,744.86 90.87,766.27 U14.5@90.87,793.8
  L10-BOT w6: R79.1@31.5,693.9 R97.2@31.5,739.17 36.03,743.71 v1(55.01,743.71)
NetR81_1: R81.1 R82.2 | length 45.8
  L01-TOP w6: R81.1@846.46,1533.46 857.28,1522.64 R82.2@857.28,1492.13
NetR81_2: R81.2 R83.1 R84.2 | length 800.5
  L01-TOP w6: v1(765.42,1838.92) 765.42,1756.46 818.9,1702.98 818.9,1614.17 823.52,1609.56 R84.2@846.64,1609.56 846.46,1609.37 R81.2@846.46,1568.9 ; R83.1@987.2,2153.54 988.19,2152.56 v1(988.19,2122.05)
  L03-SIG w5.5: v1(765.42,1838.92) 765.33,1839.01 765.33,1879.12 cw(c813.79,1879.12) 767,1891.73 768.43,1893.16 cw(c826.77,1834.81) 826.77,1917.32 924.24,1917.32 ccw(c924.24,1957.65) 943.29,1922.11 958.36,1937.17 ccw(c902.95,1992.57) 976.08,1964.46 ccw(c902.95,1992.57) 981.3,1992.57 981.3,2105.41 cw(c1004.82,2105.41) v1(988.19,2122.05)
NetR82_1: R82.1 Y5.3 | length 55.4
  L01-TOP w6: R82.1@890.75,1492.13 892.72,1490.16 Y5.3@892.72,1438.98 Y5.3@893.7,1439.96
NetR85_1: R85.1 R86.2 | length 49.5
  L10-BOT w6: R86.2@807.09,2083.66 ccw(c809.46,2086.04) 809.46,2082.68 R85.1@856.3,2082.68
NetR85_2: R85.2 R87.1 R88.2 | length 95.5
  L10-BOT w6: R85.2@891.73,2082.68 R87.1@987.2,2082.68
NetR98_2: R98.2 U14.14 | length 81.2
  L01-TOP w6: v1(47.24,921.26) 65.38,921.26 71.18,915.46 U14.14@71.18,889.27
  L01-TOP w10: U14.14@71.1,889.35 U14.14@71.18,889.27
  L10-BOT w6: v1(47.24,921.26) 47.24,946.37 R98.2@49.69,948.82
NetR102_1: R102.1 R103.2 | length 39
  L10-BOT w6: R102.1@388.56,1468.02 388.78,1467.81 R103.2@388.78,1429.13
NetR102_2: R102.2 R104.1 R105.2 | length 100.6
  L10-BOT w6: R104.1@342.52,1512.8 349.07,1519.35 349.07,1528.94 361.82,1541.69 R105.2@386.47,1541.69 386.47,1505.55 R102.2@388.56,1503.46
NetR103_1: R103.1 Y7.3 | length 181.9
  L01-TOP w6: Y7.3@384.84,1328.74 392.72,1336.61 392.72,1365.26 426.81,1365.26 v1(458.98,1397.42)
  L10-BOT w6: R103.1@422.24,1429.13 448.82,1429.13 458.98,1418.97 v1(458.98,1397.42)
NetR106_1: R106.1 R107.2 | length 43.1
  L10-BOT w6: R107.2@401.57,1817.91 401.57,1777.56 R106.1@403.54,1775.59
NetR106_2: R106.2 R108.1 R109.2 | length 86.3
  L10-BOT w6: R108.1@366.14,1690.94 365.18,1691.91 R109.2@365.18,1731.3 368.11,1734.23 R106.2@368.11,1775.59
P1V8: C42.1 C44.1 C48.2 C73.1 C74.1 C75.1 C79.1 C89.1 C99.1 C111.1 L4.1 L5.1 L7.1 L9.2 L12.1 L15.1 R15.1 R51.1 | length 704.5
  L10-BOT w15: R15.1@130.24,754.87 133.47,751.64 157.37,751.64 161.09,747.92 167.45,747.92 198.83,716.54 232.28,716.54 271.65,677.17 ; R51.1@256.89,1016.31 257.87,1016.31 260.22,1018.65 260.22,1035.54 275.59,1050.91 v1(275.59,1051.18) ; L15.1@407.54,1287.4 405.85,1289.09 405.85,1356.58 C74.1@404.15,1358.27 406.74,1360.85 421.84,1360.85 430.09,1369.09 430.09,1397.42 v1(430.22,1397.56) ; v1(826.15,1396.59) 826.28,1396.72 C75.1@869.02,1396.72 ; L4.1@869.04,1346.59 C75.1@869.02,1396.72 ; L12.1@909.45,669.29 909.01,668.86 909.01,627.55 C99.1@908.58,627.12 939.81,627.12 v1(940.94,625.98) ; L7.1@952.76,921.43 952.79,921.39 997.23,921.39 C89.1@997.27,921.35 997.27,890.95 v1(997.98,890.24) ; L5.1@968.5,1118.11 969.6,1119.21 1011.9,1119.21 C79.1@1012.56,1119.87 ; C73.1@1012.13,1074.8 1012.56,1075.24 C79.1@1012.56,1119.87 ; v1(1012.99,1141.73) C79.1@1012.99,1120.31 C79.1@1012.56,1119.87
  other v1: 964.57,570.87 964.47,594.39 964.57,618.11 279.53,637.8 303.15,637.8 326.77,637.8
P1V8_PGOOD: Q2.1 R54.1 U14.4 | length 862.8
  L01-TOP w8: v1(61.98,766.27) 63.51,767.8 63.51,777.76 71.18,785.43 U14.4@71.18,793.8
  L06-PWR w5: v1(61.98,766.27) 74.8,753.44 74.8,640.83 47.24,613.27 47.24,484.25 129.92,401.57 327.47,401.57 v1(359.1,433.21)
  L10-BOT w6: v1(61.98,766.27) 110.55,717.69 110.55,714.39 118.25,706.69 Q2.1@153.54,706.69 ; v1(359.1,433.21) 378.94,453.04 R54.1@378.94,480.32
